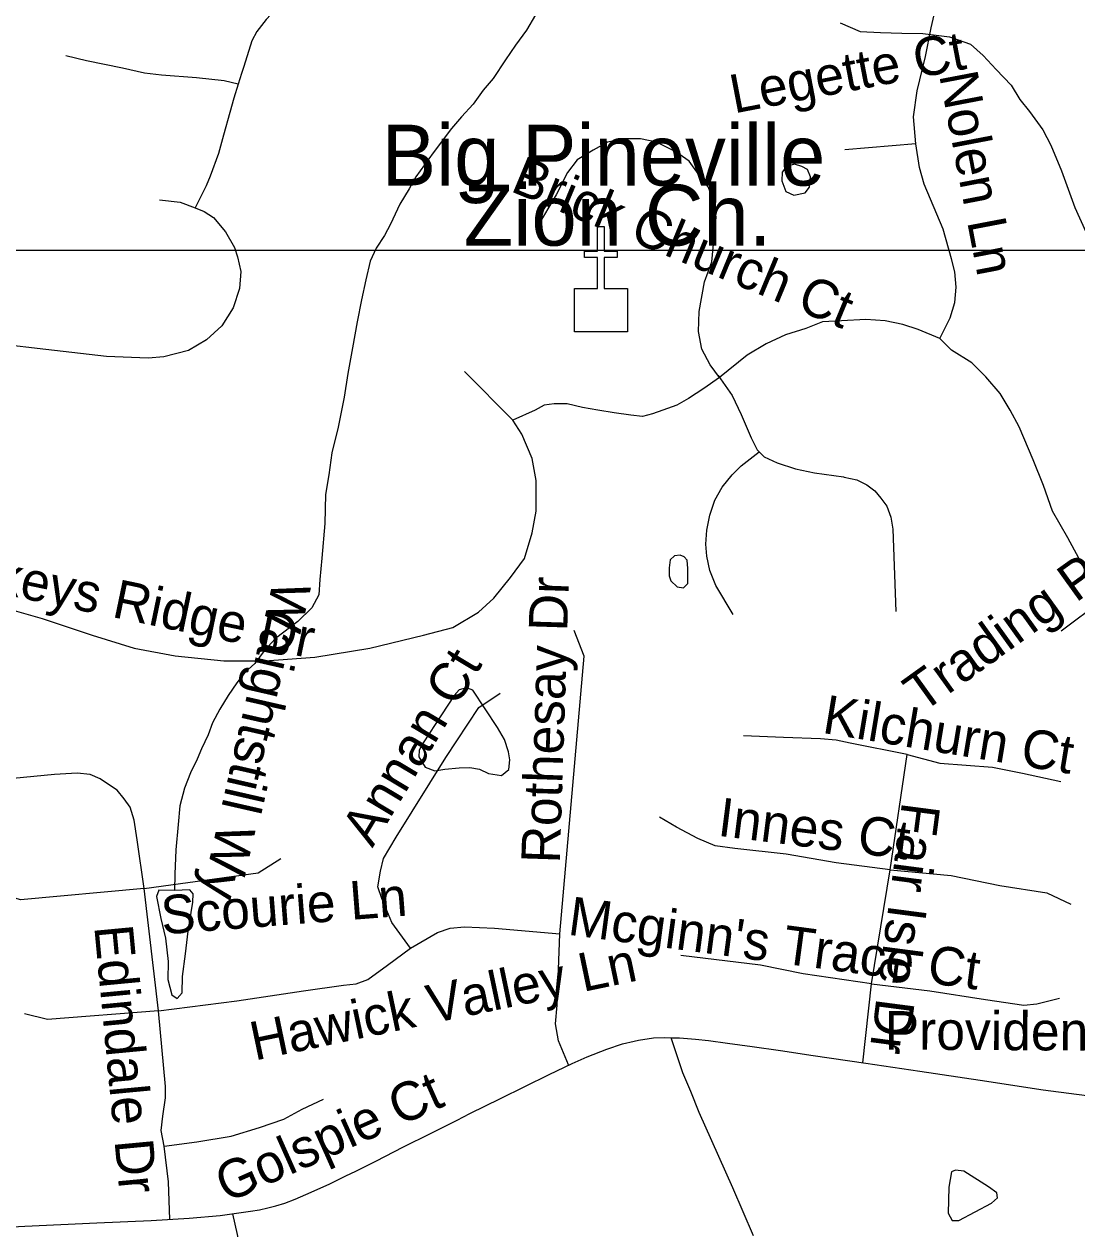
# Model space of a CAD drawing. Extents: x 1383679 to 1536984, y 460658 to 651027.
# Drawn here: x 1442977 to 1445570, y 474906 to 477874 of the extents above; entities that cross this region are included whole.
import ezdxf

# ---------------------------------------------------------------- set-up
doc = ezdxf.new("R2010")
doc.units = 0
for name, color, linetype in [('Exist Cultural Church CELL', 7, 'Continuous'), ('Exist Cultural Church Label', 7, 'Continuous'), ('Exist Hydrographic Misc Water Feature', 7, 'Continuous'), ('Exist Road Non-System Type 51', 7, 'Continuous'), ('Exist Road Non-System Type 51 Label', 7, 'Continuous'), ('Exist Road Secondary Type 51 Attributed', 7, 'Continuous'), ('Map Preparation Inset Cut Line', 7, 'Continuous')]:
    doc.layers.add(name, color=color, linetype=linetype)

msp = doc.modelspace()

# ---------------------------------------------------------------- linework, layer by layer
at = {"layer": 'Exist Cultural Church CELL'}
msp.add_lwpolyline([(1444332.3, 477222.4), (1444389.2, 477222.6), (1444389.2, 477298.7), (1444357.2, 477298.7), (1444357.2, 477314.7), (1444389.2, 477314.7), (1444389.2, 477374.8), (1444405.3, 477374.8), (1444405.3, 477314.7), (1444437.3, 477314.7), (1444437.3, 477298.7), (1444405.3, 477298.7), (1444405.3, 477222.6), (1444462.9, 477222.4), (1444462.9, 477116), (1444332.3, 477116)], close=True, dxfattribs=at)
at = {"layer": 'Exist Hydrographic Misc Water Feature'}
for points in [[(1444236.7, 477896.3), (1444214, 477859), (1444187.3, 477821.7), (1444162.7, 477786.2), (1444131.8, 477740), (1444107.3, 477711), (1444082.6, 477677), (1444054, 477645.6), (1444029.5, 477616.5), (1443984.4, 477556.7), (1443941.3, 477497.7), (1443924.8, 477468.4), (1443902, 477430.4), (1443879.1, 477380.7), (1443864.6, 477353.1), (1443844.1, 477321.5), (1443829.4, 477289.8), (1443818.6, 477244.1), (1443807.6, 477194.2), (1443796.7, 477140.3), (1443785.5, 477076.5), (1443774.4, 477012.8), (1443765.3, 476954.7), (1443750, 476881.1), (1443734.8, 476817.4), (1443727.7, 476763.4), (1443718.9, 476715.2), (1443717.6, 476643.8), (1443710, 476557.8), (1443705.1, 476505.4), (1443702.4, 476467.7), (1443685.8, 476436), (1443651.1, 476402.2), (1443596.3, 476359.8), (1443567.7, 476330), (1443545.2, 476298.5), (1443520.8, 476276.8)], [(1444986.7, 477877.1), (1445036.3, 477855.5), (1445086.3, 477852.9), (1445138.3, 477851.8), (1445190.3, 477850.8), (1445256.1, 477842.1), (1445307.9, 477824.6), (1445339.3, 477796.1), (1445370.7, 477761.8), (1445408, 477723.3), (1445429.5, 477688.4), (1445452.8, 477658.4), (1445486.2, 477613.5), (1445505.4, 477575.3), (1445532.3, 477512.4), (1445564.6, 477422.3), (1445591.6, 477361.9)], [(1444854.2, 477522.8), (1444843.8, 477509), (1444843.5, 477487.7), (1444853.1, 477461.3), (1444872.8, 477452.7), (1444900.9, 477457.8), (1444911.2, 477472.4), (1444913.8, 477497.8), (1444906.1, 477516), (1444892.2, 477522.8), (1444874.3, 477528.9), (1444854.2, 477522.8)], [(1444592.5, 476565.4), (1444578.5, 476564.1), (1444568.3, 476553.7), (1444566, 476534), (1444565.6, 476514.3), (1444569.4, 476501.9), (1444585.1, 476487.7), (1444601.2, 476484.9), (1444611.3, 476495.3), (1444611.7, 476515), (1444611.9, 476533), (1444610.3, 476552.8), (1444602.5, 476561.1), (1444592.5, 476565.4)], [(1443520.8, 476276.8), (1443500.3, 476251), (1443479.7, 476219.4), (1443459.1, 476186.2), (1443440.5, 476152.1), (1443429.9, 476122.8), (1443413.3, 476088.6), (1443402.8, 476062.6), (1443386.2, 476029.3), (1443371.6, 475991.8), (1443360.7, 475947.7), (1443355.9, 475901.9), (1443350.7, 475839.6), (1443347.6, 475779.8), (1443346.9, 475739.6)], [(1444005.1, 476171.9), (1443959.9, 476103.1), (1443949.5, 476085.2), (1443949.2, 476068.8), (1443964.8, 476043.1), (1443988.6, 476034.4), (1444012.7, 476038), (1444048.7, 476041.4), (1444074.7, 476042.5), (1444098.8, 476037.9), (1444120.5, 476027.6), (1444152.4, 476022.9), (1444170.8, 476037.3), (1444173.1, 476061), (1444169.5, 476080.8), (1444160, 476111.4), (1444142.6, 476141.2), (1444082.3, 476232.7), (1444066.4, 476238.8), (1444048.2, 476233.4), (1444036, 476219.7), (1444005.1, 476171.9)], [(1443346.9, 475739.6), (1443308.8, 475740.4), (1443302.6, 475724.9), (1443313.6, 475670.5), (1443324.7, 475621.8), (1443331.7, 475564.3), (1443330.9, 475520), (1443340.2, 475482.1), (1443354, 475473.5), (1443366.3, 475487.3), (1443367, 475527.5), (1443374.1, 475583.1), (1443381.1, 475638.8), (1443392.4, 475710.7), (1443392.8, 475731.2), (1443385, 475741.3), (1443346.9, 475739.6)], [(1445352.5, 475009.1), (1445291.2, 475048.1), (1445271.2, 475050.1), (1445261.1, 475046.2), (1445254.5, 475008.6), (1445253.2, 474944.6), (1445263, 474926.4), (1445279, 474926.1), (1445359.7, 474968.7), (1445374, 474982.4), (1445372.3, 474994.7), (1445352.5, 475009.1)]]:
    msp.add_lwpolyline(points, dxfattribs=at)
at = {"layer": 'Exist Road Non-System Type 51'}
for points in [[(1445173.4, 477578.6), (1445167.5, 477645.7), (1445176.3, 477709.8), (1445196.7, 477794.4), (1445211.3, 477864.4), (1445231.7, 477954.9), (1445249.1, 478033.6), (1445252.1, 478068.6), (1445252.1, 478121.1), (1445243.3, 478173.6), (1445231.7, 478220.3), (1445214.2, 478258.2), (1445193.8, 478293.2), (1445170.4, 478325.3)], [(1443663.1, 477985), (1443616.9, 477933.1), (1443572.9, 477885.1), (1443549.8, 477855.6), (1443537.8, 477832.3), (1443517.8, 477769.8), (1443512, 477751.9), (1443504.2, 477726.2)], [(1443504.2, 477726.2), (1443469.9, 477734.1), (1443401.1, 477741.2), (1443314.8, 477747.7), (1443273.2, 477753.2), (1443218.9, 477765.2), (1443130.1, 477783.7), (1443079.9, 477795.6)], [(1443504.2, 477726.2), (1443493.6, 477691.3), (1443483.1, 477656.2), (1443467.8, 477600.1), (1443455.9, 477554.9), (1443434.9, 477499.2), (1443424.8, 477475.5), (1443398.2, 477421.1)], [(1444689.4, 477003.6), (1444666.6, 477034.5), (1444646.2, 477072.7), (1444638, 477116.4), (1444639.4, 477165.5), (1444653, 477239.2), (1444670.6, 477288.5), (1444674.6, 477331.9), (1444681.6, 477397.4), (1444677.6, 477433.3), (1444661.8, 477472.7), (1444638.2, 477504.3), (1444614.6, 477535.8), (1444581.7, 477559.3), (1444534.4, 477582.9), (1444495.2, 477591.1), (1444455.8, 477591.1), (1444413.7, 477583.1), (1444378.2, 477563.4), (1444338.8, 477539.7), (1444315.2, 477508.2), (1444287.6, 477453), (1444240.3, 477374.2)], [(1445173.4, 477578.6), (1444998.5, 477564)], [(1445232.6, 477099.1), (1445257.9, 477149.8), (1445269.6, 477187.7), (1445272.5, 477225.6), (1445269.6, 477263.5), (1445260.8, 477295.6), (1445240.4, 477368.6), (1445193.8, 477479.4), (1445182.1, 477520.2), (1445173.4, 477578.6)], [(1443310.6, 477440.7), (1443360.8, 477435.3), (1443398.2, 477421.1)], [(1443398.2, 477421.1), (1443420.4, 477411.9), (1443443.1, 477397), (1443473, 477362.3), (1443494.9, 477323.8), (1443502.4, 477300.5), (1443510.9, 477264), (1443507.6, 477222.4), (1443491.4, 477174.7), (1443463.8, 477130.8), (1443425.6, 477096.1), (1443381.4, 477069.8), (1443321.2, 477054.5), (1443281.9, 477051.1), (1443179.6, 477055.3), (1443030.4, 477072.4), (1442918, 477085.5)], [(1445232.6, 477099.1), (1445179.2, 477121.1), (1445141.4, 477133.7), (1445097.4, 477143.2), (1445050.2, 477146.3), (1444990.4, 477143.2), (1444943.2, 477140), (1444902.4, 477124.3), (1444852, 477108.5), (1444804.8, 477086.5), (1444757.7, 477058.2), (1444689.4, 477003.6)], [(1445632.1, 476453.8), (1445585, 476538.8), (1445547.2, 476608), (1445509.5, 476674.1), (1445487.4, 476737.1), (1445462.3, 476800), (1445427.7, 476881.9), (1445405.7, 476922.8), (1445380.5, 476963.7), (1445345.9, 477004.7), (1445311.3, 477039.3), (1445261, 477070.8), (1445232.6, 477099.1)], [(1444180.9, 476897.9), (1444061.2, 477017.8)], [(1444689.4, 477003.6), (1444650.7, 476976.3), (1444613, 476951.1), (1444584.6, 476935.4), (1444550, 476922.8), (1444524.9, 476913.4), (1444499.7, 476907.1), (1444471.4, 476910.2), (1444430.5, 476916.5), (1444389.6, 476922.8), (1444351.9, 476929.1), (1444314.1, 476938.5), (1444282.7, 476938.5), (1444257.5, 476935.4), (1444235.5, 476922.8), (1444180.9, 476897.9)], [(1444686.1, 477008.2), (1444720.5, 476958.8), (1444742.8, 476911.7), (1444767.5, 476854.8), (1444782.4, 476825.1), (1444787.4, 476820.1)], [(1442911.1, 476440.7), (1443021.3, 476409.2), (1443144.2, 476368.2), (1443248.2, 476336.6), (1443349.1, 476317.7), (1443468.8, 476305.1), (1443569.6, 476305.1), (1443692.5, 476314.6), (1443828, 476336.6), (1443960.4, 476368.2), (1444032.8, 476387.1), (1444095.8, 476424.9), (1444133.7, 476459.6), (1444174.6, 476510.1), (1444209.3, 476557.4), (1444228.2, 476620.4), (1444237.6, 476674), (1444237.6, 476749.7), (1444228.2, 476803.3), (1444203, 476863.2), (1444180.9, 476897.9)], [(1444722.9, 476419.1), (1444680.9, 476490.8), (1444666, 476528), (1444658.6, 476562.7), (1444656.1, 476592.3), (1444658.6, 476627), (1444666, 476664.2), (1444678.4, 476701.2), (1444695.8, 476733.4), (1444720.5, 476763.2), (1444742.8, 476785.4), (1444787.4, 476820.1)], [(1444787.4, 476820.1), (1444799.6, 476807.8), (1444831.9, 476792.8), (1444876.4, 476778), (1444923.5, 476768.1), (1444995.2, 476758.2), (1444996.8, 476757.8), (1445027.5, 476750.8), (1445052.2, 476738.4), (1445072, 476723.6), (1445086.9, 476706.2), (1445101.8, 476686.4), (1445111.6, 476659.2), (1445116.6, 476629.5), (1445124, 476426.5)], [(1445632.1, 476453.8), (1445531.5, 476378.2)], [(1444296.4, 475632.3), (1444356, 476316.5), (1444331.5, 476379.6)], [(1443928.3, 475597.2), (1443882.7, 475660.3), (1443858.2, 475720), (1443847.6, 475748.1), (1443854.7, 475786.7), (1443861.7, 475818.2), (1443893.2, 475870.9), (1444015.9, 476067.3), (1444096.6, 476190.1), (1444149.2, 476225.2)], [(1445151.9, 476074.4), (1445011.7, 476102.4), (1444976.6, 476109.4), (1444938.1, 476113), (1444846.9, 476116.5), (1444748.7, 476120)], [(1445109.9, 475790.2), (1445151.9, 476074.4)], [(1445151.9, 476074.4), (1445232.6, 476053.3), (1445362.3, 476042.8), (1445435.9, 476028.7), (1445530.6, 476007.7)], [(1443272.6, 475744.5), (1443255.1, 475863.8), (1443248.1, 475913), (1443237.6, 475944.5), (1443223.5, 475965.6), (1443206, 475986.6), (1443185, 476000.7), (1443163.9, 476014.7), (1443139.4, 476025.2), (1443107.8, 476028.7), (1443051.7, 476025.2), (1442872.9, 476007.7)], [(1445109.9, 475790.2), (1444976.6, 475807.7), (1444853.9, 475828.8), (1444727.7, 475842.8), (1444678.6, 475849.8), (1444636.5, 475867.3), (1444583.9, 475895.4), (1444541.9, 475920)], [(1443272.6, 475744.5), (1443553.1, 475783.1), (1443609.2, 475818.2)], [(1445064.3, 475509.5), (1445109.9, 475790.2)], [(1445109.9, 475790.2), (1445260.6, 475776.1), (1445379.8, 475751.6), (1445495.5, 475734), (1445555.1, 475706)], [(1443272.6, 475744.5), (1442967.6, 475716.5), (1442911.5, 475734)], [(1443307.7, 475442.8), (1443272.6, 475744.5)], [(1443928.3, 475597.2), (1443994.9, 475635.8), (1444026.5, 475646.3), (1444061.5, 475649.8), (1444135.1, 475646.3), (1444296.4, 475632.3)], [(1444317.5, 475309.5), (1444292.9, 475369.1), (1444285.9, 475411.2), (1444289.4, 475456.8), (1444292.9, 475544.6), (1444296.4, 475632.3)], [(1443307.7, 475442.8), (1443500.5, 475467.4), (1443665.3, 475491.9), (1443763.5, 475506), (1443795, 475509.5), (1443823.1, 475520), (1443872.2, 475555.1), (1443928.3, 475597.2)], [(1445064.3, 475509.5), (1444896, 475534), (1444790.8, 475555.1), (1444594.5, 475579.6)], [(1445043, 475314.7), (1445064.3, 475509.5)], [(1445064.3, 475509.5), (1445208, 475491.9), (1445344.8, 475470.9), (1445439.4, 475456.8), (1445471, 475460.3), (1445527.1, 475474.4)], [(1443307.7, 475442.8), (1443034.2, 475421.7), (1442978.1, 475435.8)], [(1443321.7, 475109.5), (1443314.7, 475148.1), (1443318.2, 475183.2), (1443325.2, 475228.8), (1443325.2, 475256.8), (1443307.7, 475442.8)], [(1442870.6, 474906.3), (1442978.4, 474912.3), (1443156.2, 474920.3), (1443289.7, 474926.7), (1443383.2, 474932), (1443460, 474938.7), (1443534.2, 474949.1), (1443556.9, 474953), (1443577.4, 474957.2), (1443596.5, 474962.9), (1443618.7, 474969.4), (1443644.1, 474979), (1443684.1, 474996.2), (1443730, 475016.8), (1443768.9, 475036.6), (1443793.5, 475048.2), (1443844.8, 475073.6), (1443909.6, 475106.9), (1443979.2, 475141.8), (1444043.5, 475173.9), (1444075, 475189.6), (1444150.4, 475227.1), (1444270.3, 475285.9), (1444326.9, 475313), (1444363.7, 475329.2), (1444412.3, 475348.7), (1444450.6, 475361.3), (1444479.2, 475368.2), (1444489.9, 475370.7), (1444526.7, 475376), (1444554.1, 475376.8), (1444570.5, 475376.7)], [(1444570.5, 475376.7), (1444591, 475376.6), (1444630.1, 475373), (1444662.2, 475369.8), (1444709.1, 475363.5), (1444769.9, 475355.2), (1444839.8, 475344.9), (1444920.2, 475333), (1445050.4, 475313.7), (1445182.8, 475294.5), (1445331.3, 475271.7), (1445487.1, 475248.3), (1445569.3, 475237.3), (1445632.6, 475229.6)], [(1443321.7, 475109.5), (1443402.4, 475120), (1443486.5, 475134), (1443556.6, 475155.1), (1443616.2, 475176.1), (1443661.8, 475200.7), (1443714.4, 475225.3)], [(1443335.7, 474928.9), (1443332.2, 475021.8), (1443321.7, 475109.5)], [(1445352.5, 475009.1), (1445291.2, 475048.1), (1445271.2, 475050.1), (1445261.1, 475046.2), (1445254.5, 475008.6), (1445253.2, 474944.6), (1445263, 474926.4), (1445279, 474926.1), (1445359.7, 474968.7), (1445374, 474982.4), (1445372.3, 474994.7), (1445352.5, 475009.1)], [(1443489.9, 474942.8), (1443501.4, 474891.9), (1443505.9, 474869.6), (1443513.9, 474846.4), (1443534.4, 474786.8)]]:
    msp.add_lwpolyline(points, dxfattribs=at)
at = {"layer": 'Exist Road Secondary Type 51 Attributed'}
msp.add_lwpolyline([(1444773.4, 474888.3), (1444722.1, 475006.7), (1444670.4, 475123), (1444639.6, 475192.5), (1444618.6, 475244.2), (1444599.6, 475290.3), (1444570.5, 475376.7)], dxfattribs=at)
at = {"layer": 'Map Preparation Inset Cut Line'}
for points in [[(1446195.4, 477316), (1383679.3, 477316), (1383679.3, 520758.2), (1458567.8, 520758.2), (1458567.8, 493672.2), (1446195.4, 493672.2), (1446195.4, 477316)], [(1437474.3, 477316), (1437474.3, 461213.3), (1475802.8, 461213.3), (1475802.8, 477316), (1437474.3, 477316)]]:
    msp.add_lwpolyline(points, dxfattribs=at)

# ---------------------------------------------------------------- texts
at = {"layer": 'Exist Cultural Church Label'}
for s, p in [('Big Pineville', (1443857.8, 477476.1)), ('Zion Ch.', (1444059.3, 477328.1))]:
    msp.add_text(s, height=150, dxfattribs=at).set_placement(p)
at = {"layer": 'Exist Road Non-System Type 51 Label'}
for s, rotation, p in [('Legette Ct', 10.883, (1444725.4, 477653.5)), ('Nolen Ln', 280.8287, (1445230.3, 477748.6)), ('Brick Church Ct', 337.4778, (1444171.6, 477463.3)), ('Trading Path Wy', 35.6808, (1445188.6, 476175.3)), ('Jockeys Ridge Dr', 348.2294, (1442706.5, 476514.4)), ('Waightstill Wy', 257.1388, (1443591, 476507.5)), ('Rothesay Dr', 88.1572, (1444296.1, 475805.2)), ('Annan Ct', 59.0825, (1443834.6, 475842.9)), ('Kilchurn Ct', 350.581, (1444940.2, 476128.1)), ('Innes Ct', 352.8284, (1444682.9, 475874.5)), ('Fair Isle Dr', 262.5604, (1445139.5, 475959.5)), ('Scourie Ln', 4.4061, (1443317.4, 475631.1)), ("Mcginn's Trace Ct", 352.3477, (1444313.8, 475630.8)), ('Edindale Dr', 275.3978, (1443149.4, 475650.6)), ('Hawick Valley Ln', 11.8158, (1443544.7, 475320.1)), ('Providence Rd West', 359.721, (1445096.3, 475347.4)), ('Golspie Ct', 24.0361, (1443475.4, 474968.6))]:
    msp.add_text(s, height=95, rotation=rotation, dxfattribs=at).set_placement(p)

doc.saveas('drawing.dxf')
